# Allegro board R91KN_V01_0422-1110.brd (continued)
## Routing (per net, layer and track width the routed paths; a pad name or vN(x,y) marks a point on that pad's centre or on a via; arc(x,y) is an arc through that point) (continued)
VDDC_LGATE: length 8.5
  TOP w0.8: R622.2 57.77,98.79 57.77,103.8 57.02,104.55 57.02,104.55 56.79,104.78 Q603.4
VDDC_LGATE_CTR: length 3.4
  TOP w0.8: U601.4 61.02,100.26 R615.1 61.01,98.6 R622.1
VDDC_PHASE: length 37.4
  TOP w0.503: 45.61,97.79 L601.1 ; L601.1 45.09,96.36 ; L601.1 45.61,94.93 ; L601.1 48.47,94.93 ; L601.1 47.04,98.31 ; L601.1 48.99,96.36 ; L601.1 47.04,94.4 ; L601.1 48.47,97.79
  TOP w0.8: v2(65.04,107.3) C605.2 65.04,105.76 U601.8
  BOTTOM w1: v2(65.04,107.3) 63.74,106 60.15,106 58.25,107.9 v2(48.55,107.9)
VDDC_SV: length 3.6
  TOP w0.1: R600.2 71.55,98.61 C613.1 70.36,99.8 R611.2
VDDC_UGATE: length 1.7
  TOP w0.8: Q601.4 46.44,104.94 R621.2
VDDC_UGATE_CTR: length 21.8
  TOP w0.8: U601.2 60.17,102.97 59.31,103.84 59.31,104.8 58.22,105.89 58.22,107.8 56.72,109.3 46.79,109.3 45.46,107.97 R621.1
VDDC_VCC: length 4.4
  TOP w0.8: C603.1 64.75,98.27 R607.2 66.73,100.26 U601.5
+DPAB_18: length 19.7
  TOP w0.2: U1.AG8 81.29,65.34 v1(81.29,65.3) 81.37,65.38 81.9,65.38 82.16,65.12 82.16,64.74 81.75,64.33 U1.AG10
  TOP w0.3: 82.28,62.6 v1(82.28,62.6) ; 82.28,62.6 82.26,62.59 82.26,62.45 82.47,62.25 82.47,62.2 82.55,62.11 U1.AF13 ; 82.28,62.6 82.26,62.62 82.26,62.91 U1.AF11 ; U1.AE11 83.35,63.16 83.04,62.86 v1(83.04,62.6) 83.04,62.52 83.35,62.22 U1.AE13
  BOTTOM w0.4: C2511.2 80.66,64.72 81.1,65.16 81.15,65.16 v1(81.29,65.3) 81.48,65.3 82.25,64.53 82.25,63.9 C2513.2 82.27,63.8 82.27,62.67 82.31,62.63 ; 82.31,62.63 82.35,62.59 83.03,62.59 v1(83.04,62.6) ; 82.31,62.63 82.28,62.6 v1(82.28,62.6)
  BOTTOM w0.5: C2511.2 80.56,64.74 C2510.2 79.01,65.31 78.51,65.31 78.5,65.31 78.02,65.31 v4(77.89,65.44) 76.77,65.44 C2512.1 76.54,65.5 74.7,65.5 C2509.1 73.42,64.22 C2514.2 73.42,63.32 B2503.2
+DPAB_VDD10: length 9.7
  TOP w0.3: U1.AF6 U1.AF7 82.55,66.55 v1(82.9,66.2) 82.9,66.15 U1.AF8 82.55,65.74 82.41,65.6 82.41,65.36 82.5,65.27 82.5,65.05 U1.AF9
  BOTTOM w0.4: v1(82.9,66.2) 82.64,66.46 C2517.2
  BOTTOM w0.5: 77.87,66.8 77.9,66.83 78.3,66.83 78.31,66.83 78.8,66.83 78.81,66.83 v4(79.44,66.83) 80.42,66.83 80.48,66.88 C2516.2 80.68,66.8 81.65,66.8 81.99,66.46 C2517.2 ; 77.87,66.8 B2505.2 ; 77.87,66.8 C2515.1
+DPC_18: length 6.9
  TOP w0.2: 87.76,67.01 86.89,67.01 v1(86.56,66.67) 86.51,66.67 86.16,67.03 85.32,67.03 U1.AC6
  TOP w0.25: 87.76,67.01 U1.W6
  TOP w0.3: U1.AC6 U1.AC5
  BOTTOM w0.4: v1(86.56,66.67) 86.56,67.19 B800.2 86.42,67.66 C800.2
+DPC_VDD10: length 8.6
  TOP w0.25: B801.2 C801.2 88.05,72.99 88.05,72.35 87.05,71.35 87.05,70 86.95,69.9 86.95,68.45 86.7,68.2 U1.AA5 U1.AA6
+DPEF_18: length 13.9
  TOP w0.3: U1.AG15 82.35,60.2 v3(82.36,60.2) 82.55,60.01 U1.AF16 81.95,59.6 U1.AG16 81.73,59.4 v3(81.33,58.99) 81.35,58.99 U1.AG17 U1.AG18 U1.AG19
  BOTTOM w0.5: C1504.2 82.23,59.42 82.23,60.07 v3(82.36,60.2) ; B1500.2 75.72,58.7 v4(75.83,58.81) 77,58.81 C1500.1 78.19,58.83 C1501.2 78.36,58.71 79.06,58.71 C1502.2 80.18,58.86 C1503.1 80.74,58.29 C1505.2 81.5,58.81 81.33,58.98 v3(81.33,58.99)
+DPEF_VDD10: length 8.5
  TOP w0.4: v1(82.31,55.34) 82.55,55.11 U1.AF22 82.35,54.6 U1.AG22 U1.AG21 U1.AG20
  BOTTOM w0.4: v1(82.31,55.34) 82.73,54.93 C1508.2
  BOTTOM w0.5: B1502.2 78.45,55.88 79.4,55.88 C1506.1 79.53,55.76 80.55,55.76 C1507.2 81.89,55.77 v1(82.31,55.34)
+DPLL_PVDD: length 11.8
  TOP w0.3: v1(82.68,61.4) 82.68,61.36 82.53,61.2 82.53,60.83 U1.AF14
  BOTTOM w0.3: v1(82.68,61.4) 82.64,61.44 82.07,61.44 81.8,61.71 81.8,61.72 81.58,61.93 81.02,61.93 C59.1
  BOTTOM w0.4: C59.1 C64.1 78.73,62.48 C63.1
  BOTTOM w0.5: B7.2 74.18,62.6 74.18,63.08 74.66,63.56 74.66,63.64 ; C88.1 74.66,63.64 ; 74.66,63.64 74.84,63.64 75.77,62.71 77.82,62.71 C63.1
+DPLL_VDDC: length 18.6
  TOP w0.3: v1(83.55,60.24) 84.1,60.8 U1.AD14
  L3_INNER w0.2: v5(71.86,61.29) 71.87,61.3 74.85,61.3 75.85,60.3 78.85,60.3 79.15,60 81.72,60 82.15,59.56 82.43,59.56 82.86,60 83.31,60 v1(83.55,60.24)
  BOTTOM w0.3: C67.1 82.99,59.7 83.47,60.17 83.47,60.17 v1(83.55,60.24)
  BOTTOM w0.5: v5(71.86,61.29) 71.78,61.37 71.73,61.41 71.73,61.92 C66.1 71.23,62.42 C68.1 70.24,62.59 69.06,62.59 B8.2
+MPV18: length 17.2
  TOP w0.3: U1.L8 94.35,65.86 93.78,66.44 93.78,66.46 93.77,66.46 93.77,66.45 93.76,66.45 93.76,66.46 v1(93.72,66.46)
  BOTTOM w0.4: B12.2 94.02,77.28 C78.1 C77.1 90.83,74.22 91.72,73.33 91.72,70.92 92.83,69.8 C79.1 92.83,66.62 C80.1 93.06,66.46 93.72,66.46 v1(93.72,66.46)
+MVDD: length 290.4
  TOP w0.097: U202.R1 v1(139.56,48.02)
  TOP w0.2: 132.56,78.17 132.49,78.1 v1(131.91,78.1) ; v3(134.77,74.44) 134.75,74.42 134.75,74.2 134.33,73.78 133.83,73.78 133.44,74.17 133.37,74.17 ; v1(139.54,38.24) 139.44,38.24 139.26,38.41 U202.C1 ; 132.56,39.22 132.06,39.22 132.04,39.23 131.13,39.23 130.68,38.78 v1(130.32,38.78)
  TOP w0.3: v1(131.97,70.14) 132.01,70.17 132.56,70.17 ; C122.1 127.04,48.32 v3(127.44,47.91) 127.96,47.4 R203.1 ; 130.3,78.85 C383.1 MC383.1 ; 130.3,78.85 130.32,78.85 v1(130.78,79.3) ; 130.3,78.85 v1(130.72,78.44) ; C125.1 124.07,63.85 v1(123.56,63.34) ; C328.2 121.81,73 v1(122.36,72.45) ; C355.1 139.54,59.16 v1(139.41,59.03) 139.39,59.01 C126.1 ; U1.K23 95.75,53.4 ; U1.K23 95.6,54.05 95.9,54.05 U1.J23 ; U1.K23 95.35,53.78 94.89,53.33 v1(94.88,53.33) 95.2,53 U1.K24 95.75,53.4 ; 95.75,53.4 U1.J24 96.21,53 v1(96.61,53.4) 96.62,53.4 96.62,53.41 96.23,53.8 U1.J23 ; 95.75,53.4 U1.J23 ; v1(97.41,59.05) 97.41,59.17 96.97,59.6 U1.H16 ; 138.16,39.22 138.18,39.22 v1(138.57,39.6) ; v1(117.89,81.44) 117.53,81.08 C351.2 ; v1(144.25,68.3) 143.85,67.9 R205.1 ; U401.E9 139.87,76.58 v1(139.97,76.67) ; C312.2 129.87,40.1 v1(130.14,40.38) 130.3,40.22 130.61,40.22 130.81,40.02 132.56,40.02 ; U401.R9 v1(139.56,68.58) ; v1(142.96,39.46) 142.96,39.49 142.46,39.99 C338.2 ; v1(133.76,43.62) 133.37,44.01 133.37,44.02 ; v3(142.87,54.16) 142.85,54.18 C377.1 ; C344.2 129.97,41.1 130.15,41.27 v1(130.16,41.27) 130.86,41.27 v1(130.87,41.27) ; v1(96.6,61.35) 96.6,61.35 96.95,61.7 U1.H13 ; v1(133.78,77.78) 133.37,77.38 133.37,77.38 ; C373.1 138.77,86.1 v3(139.11,85.75) ; v1(125.36,27.33) 125.81,27.77 C142.1 ; C356.1 136.82,58.75 137.21,58.36 v1(137.59,58.36) ; 133.37,78.97 133.35,78.97 v1(132.96,79.38) 132.56,79.77 132.56,79.78 ; v1(138.57,80.61) 138.57,80.49 138.22,80.14 138.22,79.83 U401.A8 v1(137.76,79.38) ; 132.56,75.78 131.36,75.78 131.12,76.01 131.06,76.01 v1(130.76,76.3) ; v1(123.98,47.62) 123.81,47.45 123.44,47.45 C330.2 ; U1.L22 94.53,54.6 94.03,55.09 v1(94.03,55.1) 94.05,55.1 U1.L21 94.03,56.12 94.03,56.09 94.05,56.09 ; v1(133.76,72.96) 133.75,72.96 133.66,72.87 133.65,72.87 133.53,72.75 133.53,72.75 133.37,72.58 ; 133.37,36.81 v1(133.76,37.22) ; MC365.1 142.74,64.1 v3(142.14,63.49) ; 132.56,46.41 132.53,46.45 131.99,46.45 v1(131.98,46.47) ; v1(131.68,42.47) 132.51,42.47 132.56,42.41 ; C372.1 v1(142.05,75.8) ; 132.56,68.58 131.95,68.58 v1(131.91,68.53) ; C358.1 122.51,65.53 v1(122.3,65.31) ; C326.2 v3(129.85,76.8) ; 137.37,74.97 137.31,74.97 v1(136.94,75.34) ; U202.K2 137.78,43.62 v1(137.76,43.62) ; v1(98.05,44.79) 98.49,44.35 C334.2 ; v1(137.76,42.81) 137.76,42.74 138.09,42.41 U202.H2 ; 132.56,48.02 131.96,48.02 v1(131.91,48.06) ; C309.2 142.46,41.19 142.95,40.7 v1(142.95,40.6) ; 134.16,41.62 134.37,41.62 v1(134.66,41.31) ; U1.K9 95.39,65 v1(95.75,64.64) 96.11,65 U1.J9 ; C305.2 v1(142.05,77.6) ; U1.H19 96.88,57.2 v3(96.28,56.6) ; U1.K10 95.35,64.12 v1(95.72,63.75) ; v1(139.97,40.62) 139.76,40.81 U202.F1 ; v1(119.87,49.7) 119.83,49.74 C332.2 ; C353.2 118.04,65.29 118,65.33 v3(117.91,65.33) ; U1.L11 94.9,63.75 v1(95.72,63.75) ; v3(126.72,70.25) 126.8,70.17 126.8,70.15 C343.2 ; v1(139.16,36.22) 138.97,36.41 U202.A1 138.79,36.81 138.16,37.44 138.16,37.62 ; v1(131.85,37.99) 132.28,38.41 132.56,38.41 ; v1(94.05,56.09) 94.05,56.09 ; 94.05,56.09 U1.L20 ; v1(139.57,78.47) 139.56,78.47 139.27,78.17 U401.C9 ; v1(95.72,63.75) 96.15,64.17 U1.J10 ; C315.2 118.4,49.76 v1(118.45,49.71) ; v1(130.42,36.26) 129.77,36.26 129.31,36.71 C364.1 129.74,37.14 v3(130.35,37.14) ; U401.K8 138.16,72.58 v1(138.57,72.98) ; C371.1 v1(110.34,62) ; v3(144.33,41.67) 143.87,41.67 R211.1 ; U202.N1 v1(139.6,46.41) ; v1(127.49,68.69) 128.14,68.03 C300.2 ; C307.2 v1(142.46,38.21) ; U401.D9 139.56,77.38 v1(139.76,77.58) ; U401.N9 v1(139.6,70.17) ; v3(139.91,74.1) 139.83,74.17 U401.H9
  TOP w0.4: C363.1 142.09,72.94 v1(141.65,72.5) 142.21,71.94 C301.2 ; U1.L13 94.71,61.56 94.71,62.24 U1.L12 94.55,62.47 v1(94.13,62.88) 94.55,63.3 U1.L11 ; v1(130.32,38.78) 130.32,38.73 130.31,38.73 129.81,38.73 C311.2 ; C310.2 130.12,42.1 v1(130.15,42.12) ; v3(142.15,37.4) 142.98,37.4 C379.1 142.7,36.5 v3(142.15,36.5) ; v3(143.51,59.57) 143.07,59.57 C369.1 143.3,61.16 v3(143.39,61.16) ; R201.1 143.95,48.1 144.31,48.1 144.31,48.13 144.32,48.13 144.32,48.11 v3(144.32,48.11) ; v3(142.5,79.27) 143.38,79.27 C368.1 143.11,78.32 v3(142.65,78.32) ; C354.2 v3(141.56,67.03) ; R213.1 127.82,73.94 v1(127.06,73.94) ; C337.2 v1(141.95,74.9) ; C362.1 v1(141.48,73.94) ; C342.2 v1(142.05,76.7) ; v3(141.75,50.1) 142.49,50.1 C366.1 142.48,49.25 v3(141.75,49.25)
  TOP w0.503: 153.84,68.75 C726.1 ; C726.1 156.09,69.88 ; C726.1 156.09,68.75 ; C726.1 154.97,69.88 ; C726.1 156.09,69.31 ; C726.1 153.84,69.88 ; C726.1 153.84,68.19 ; C726.1 155.53,69.88 ; C729.1 162.21,69.88 ; C729.1 161.08,68.19 ; C729.1 161.08,68.75 ; C729.1 163.33,68.75 ; C729.1 163.33,69.88 ; C729.1 163.33,69.31 ; C729.1 162.77,69.88 ; C729.1 161.08,69.88 ; L701.2 163.23,77.98 ; L701.2 163.75,76.55 ; L701.2 161.8,78.5 ; L701.2 160.37,77.98 ; L701.2 160.37,75.12 ; L701.2 161.8,74.6 ; L701.2 163.23,75.12 ; L701.2 159.85,76.55
  BOTTOM w0.1: 132.56,70.17 132.56,70.17 ; 132.56,46.41 132.56,46.42
  BOTTOM w0.2: v1(133.76,72.96) 133.75,72.96 133.37,72.58 133.37,72.58 ; v1(130.76,76.3) 130.85,76.39 131.39,76.39 131.4,76.38 131.79,76.38 131.8,76.39 132.31,76.39 132.31,76.39 132.44,76.39 132.56,76.51 132.56,76.58 ; v1(136.75,77.12) 136.77,77.12 136.91,76.98 137.53,76.98 137.92,77.38 U402.D2 ; v1(133.76,43.62) 133.76,43.61 133.76,43.05 133.37,42.66 133.37,42.41 ; v1(133.76,39.62) 133.76,39.61 133.37,39.22 ; v1(131.85,37.99) 131.94,37.99 132.37,38.41 132.56,38.41
  BOTTOM w0.25: v1(138.57,72.98) 138.16,72.58 U401.K8 ; U202.K2 138.09,44.02 137.81,43.73 137.81,43.68 v1(137.76,43.62)
  BOTTOM w0.3: C136.1 v1(122.3,65.31) ; v3(143.39,61.16) 143.39,61.1 MC381.1 143.08,59.57 v3(143.51,59.57) ; C137.1 94.32,63.64 C135.1 ; C137.1 94.17,62.88 v1(94.13,62.88) ; C137.1 95.34,63.37 v1(95.72,63.75) ; 132.56,74.17 132.48,74.09 131.64,74.09 131.64,74.1 v1(131.63,74.1) 131.53,74.2 C321.2 ; v1(137.59,58.36) 137.59,58.37 C316.2 ; v1(131.97,70.14) 132.01,70.14 132.04,70.17 132.56,70.17 ; C361.1 107.75,49.5 v1(107.75,49.68) ; U402.F1 139.11,75.78 139.63,76.3 139.63,76.34 v1(139.97,76.67) ; C121.1 99.66,47.13 R293.1 ; U402.A1 138.97,79.92 138.88,80.02 138.88,80.35 138.62,80.61 v1(138.57,80.61) ; v1(107.63,71.86) 107.56,71.86 107.07,71.36 C141.1 ; 132.56,36.81 133.01,36.37 v1(133.03,36.37) ; v1(105.53,49.62) 105.53,49.83 C370.1 ; v1(127.4,67.33) 127.06,66.98 C306.2 ; R293.1 99.96,46.87 100.62,46.87 100.8,46.7 v1(100.8,46.69) 100.81,46.69 101.46,46.03 C335.2 ; R293.1 R291.1 ; v3(136.75,41.3) 137.06,41.62 137.37,41.62 ; v1(133.76,43.62) 133.37,44.01 133.37,44.02 ; v1(131.91,78.1) 132.49,78.1 132.56,78.17 ; C314.2 117.12,75.18 117.18,75.12 117.33,75.12 v1(117.56,74.89) ; U402.B2 v1(137.76,79.38) ; C303.2 101.3,73.23 101.23,73.29 v1(101,73.29) ; v3(135.06,75.47) 134.98,75.39 134.98,75.32 134.63,74.97 U402.G7 ; 132.56,40.81 132.43,40.68 132.02,40.68 131.72,40.38 131.29,40.38 130.87,40.8 v1(130.87,41.27) ; 138.97,39.22 138.97,39.23 138.59,39.6 v1(138.57,39.6) 138.57,39.62 138.96,40.02 U201.E9 ; v1(138.17,57.39) 139.02,56.54 R225.2 ; v1(130.14,40.38) 129.87,40.1 C312.2 ; v1(131.91,68.53) 131.95,68.58 132.56,68.58 ; v1(114.49,46.36) 114.77,46.36 115.06,46.07 C333.2 ; v3(127.25,46.03) 127.25,45.98 127.54,45.68 C336.2 ; U202.N1 v1(139.6,46.41) ; C129.1 115.59,34.69 115.91,35.01 115.91,35.58 v1(115.97,35.63) ; v1(94.03,55.1) 94.1,55.1 C120.1 ; v3(122.57,49.41) 123.16,50.01 C374.1 ; v1(103.03,68.44) 103.02,68.45 103.01,68.45 102.99,68.47 102.29,68.47 C128.1 102.24,68.48 C139.1 ; 132.56,77.38 132.54,77.4 132.23,77.4 132.21,77.38 131.97,77.38 v1(131.91,77.45) ; 142.17,49.68 142.12,49.68 141.75,49.3 v3(141.75,49.25) ; 142.17,49.68 v3(141.75,50.1) ; 142.17,49.68 C131.1 ; C127.1 107.44,46.53 107.39,46.59 107.39,47.24 v1(107.62,47.48) ; v1(94.88,53.33) 95.85,54.3 R302.2 95.94,54.26 96.41,53.78 96.41,53.78 96.61,53.58 v1(96.61,53.4) ; v1(139.41,59.03) 140.09,59.03 R227.2 ; U201.A8 138.16,36.06 v1(138.35,35.88) ; v1(117.89,81.44) 117.81,81.53 117.16,81.53 117.14,81.55 C325.2 ; C385.2 100.2,75.44 99.6,75.44 v3(99.6,75.43) ; v3(142.15,64.44) 142.49,64.1 MC367.1 ; v1(110.06,71.47) 110.03,71.48 109.99,71.48 109.62,71.86 C349.2 ; v1(141.6,46.7) 141.63,46.67 141.63,46.28 142.16,45.75 C357.1 ; 132.56,48.02 131.96,48.02 v1(131.91,48.06) ; v1(97.41,59.05) 97.81,59.45 98.26,59.45 98.37,59.34 98.6,59.11 98.81,58.9 C140.1 ; v3(129.93,73.52) 129.71,73.3 C302.2 ; U401.C9 139.26,78.17 v1(139.57,78.47) ; 133.37,79.78 133.34,79.78 133.15,79.58 133.15,79.56 132.97,79.38 132.96,79.38 v1(132.96,79.38) ; v1(131.98,46.47) 132.02,46.42 132.56,46.42 ; C386.2 129.64,78.19 130.48,78.19 v1(130.72,78.44) ; v1(96.6,61.35) 96.68,61.43 C134.1 ; U401.R9 v1(139.56,68.58) ; C339.2 119.8,49.84 119.87,49.77 v1(119.87,49.7) ; C384.2 101.58,43.39 v3(101.6,43.41) ; U202.C1 139.36,38.41 v1(139.54,38.24) ; U202.R1 v1(139.56,48.02) ; U201.H9 139.83,42.41 139.88,42.46 v1(139.9,42.46) ; R207.1 126.88,70.25 v3(126.72,70.25) ; v1(138.56,73.78) 138.56,73.81 138.19,74.17 U402.H2 ; v1(130.15,42.12) 130.12,42.1 C310.2 ; C308.2 114.44,66.2 v1(114.03,65.79) ; 133.37,37.62 v1(133.76,37.22) ; C341.2 124.9,63.75 125.21,64.07 125.21,64.31 125.23,64.32 v1(125.22,64.32) ; v1(130.16,41.27) 129.99,41.1 C344.2 ; v1(130.32,38.78) 130.32,38.73 130.26,38.68 129.86,38.68 C311.2 ; U401.N9 v1(139.6,70.17)
  BOTTOM w0.4: v1(141.41,69.97) 142.42,69.97 C347.2 ; C320.2 v1(141.66,70.99) ; v1(142.95,40.6) 142.46,41.09 C309.2 ; C375.1 v1(141.6,46.7) ; C338.2 142.46,39.96 v1(142.96,39.46) ; C326.2 v3(129.85,76.8) ; v1(95.75,64.64) 95.83,64.56 C124.1 ; v1(141.51,68.97) 142.42,68.97 C348.2 ; C132.1 105.25,67.16 v3(105.25,66.3) ; v3(142.5,79.27) 143.5,79.27 MC133.1 ; C322.2 v1(141.62,47.6) ; v1(141.45,44.3) 141.75,44 C359.1 ; v3(141.72,42.29) 141.86,42.15 142.41,42.15 C340.2 ; C380.1 127.48,48.81 127.48,48.8 127.48,47.95 v3(127.44,47.91) ; C354.2 v3(141.56,67.03) ; C372.1 v1(142.05,75.8) ; C307.2 v1(142.46,38.21) ; v3(142.15,37.4) 142.98,37.4 C379.1 142.69,36.5 v3(142.15,36.5) ; v1(144.25,72.69) 143.68,72.69 R215.1 ; C342.2 v1(142.05,76.7) ; C123.1 124.12,62.93 123.7,63.34 v1(123.56,63.34) ; C337.2 v1(141.95,74.9) ; v3(141.48,67.97) 142.42,67.97 C350.2 ; R209.1 126.75,44.69 126.75,45.11 126.81,45.16 126.81,45.28 126.82,45.3 v3(126.82,45.35) ; C305.2 v1(142.05,77.6) ; C329.2 v3(141.65,43.1)
  BOTTOM w0.5: v3(140.36,84.28) 139.82,84.82 C304.2 ; C138.1 v3(119.45,87.7) ; v3(115.85,87.4) 115.85,88.44 C382.1 114.98,88.52 v3(114.98,87.47) ; v3(142.72,52.92) 143.35,52.92 MC130.1 143.33,54.16 v3(142.87,54.16)
  BOTTOM w0.503: C726.1 156.09,69.31 ; C726.1 156.09,68.75 ; C726.1 153.84,69.88 ; C726.1 154.97,69.88 ; C726.1 155.53,69.88 ; C726.1 153.84,68.75 ; C726.1 156.09,69.88 ; C726.1 153.84,68.19 ; C729.1 162.77,69.88 ; C729.1 162.21,69.88 ; C729.1 161.08,69.88 ; C729.1 163.33,68.75 ; C729.1 163.33,69.88 ; C729.1 161.08,68.19 ; C729.1 163.33,69.31 ; C729.1 161.08,68.75 ; L701.2 163.23,77.98 ; L701.2 160.37,75.12 ; L701.2 159.85,76.55 ; L701.2 163.23,75.12 ; L701.2 160.37,77.98 ; L701.2 161.8,74.6 ; L701.2 161.8,78.5 ; L701.2 163.75,76.55
  vias: v2(151.26,70.44) v2(151.64,72.72) v2(152.4,76.15) v2(152.4,73.87) v2(152.4,71.58) v2(153.16,77.3) v2(153.16,75.01) v2(153.16,72.72) v2(153.16,70.44) v2(153.92,76.15) v2(153.92,73.87) v2(153.92,71.58) v2(154.69,77.3) v2(154.69,75.01) v2(154.69,72.72) v2(154.69,70.44) v2(155.45,76.15) v2(155.45,73.87) v2(155.45,71.58) v2(156.21,77.3) v2(156.21,75.01) v2(156.21,72.72) v2(156.21,70.44) v2(156.97,76.15) v2(156.97,73.87) v2(156.97,71.58) v2(157.73,77.3) v2(157.73,75.01) v2(157.73,72.72) v2(157.73,70.44) v2(158.5,76.15) v2(158.5,73.87) v2(158.5,71.58) v2(159.26,77.3) v2(159.26,75.01) v2(159.26,72.72) v2(159.26,70.44) v2(160.02,73.87) v2(160.02,71.58) v2(160.78,72.72) v2(160.78,70.44) v2(161.54,73.87) v2(161.54,71.58) v2(162.31,72.72) v2(162.31,70.44) v2(163.07,71.58) v3(68.05,94.3) v3(68.05,92.9) v3(68.55,93.7) v3(68.95,92.9) v3(69.45,94.3) v3(69.45,93.5)
+MVDD_SOURCE: length 9.7
  TOP w0.503: C730.1 142.05,92.47 ; C730.1 141.05,93.47 ; C730.1 142.05,91.47 ; C730.1 142.05,93.47 ; C730.1 140.05,92.47 ; C730.1 140.05,91.47 ; C730.1 140.05,93.47 ; C730.1 141.05,91.47
+PCIE_PVDD: length 13.8
  TOP w0.3: U1.AM30 79.28,49 v3(78.33,48.05)
  BOTTOM w0.5: C89.1 76.95,40.7 v4(76.95,42.2) 76.95,43.2 C73.1 ; B11.2 75.65,44.49 75.99,44.15 76,44.15 C73.1 ; C73.1 77.04,43.64 77.04,44.41 78.25,45.62 78.25,46.3 C75.1 ; v3(78.33,48.05) 77.4,47.12 C74.1
  BOTTOM w0.6: C74.1 C75.1
+SPV10: length 6.4
  TOP w0.3: v1(96.55,66.24) 96.55,66.24 96.55,66.23 96.98,65.8 U1.H8
  BOTTOM w0.3: B9.2 94.45,68.49 C70.1 95.03,68.49 MB9.2 95.48,68.5 95.6,68.5 96.1,68 v4(96.1,67.72) 95.59,67.21 C71.1 95.74,66.89 96.27,66.36 96.42,66.36 v1(96.55,66.24)
+SPV18: length 12.3
  TOP w0.3: v1(97.32,67.02) 97.32,67.02 97,66.69 97,66.65 U1.H7
  BOTTOM w0.4: v1(97.32,67.02) 97.32,67.02 97.66,67.36 C62.1 97,68.84 97,69.04 C61.1
  BOTTOM w0.5: C61.1 96.22,69.82 C58.1 96.22,73.26 96.63,73.66 B5.2
A_B_DAC1: length 71.9
  TOP w0.1: U1.AH24 80.7,52.75 80.35,52.75 80.25,52.65 80.05,52.65 79.97,52.73 79.5,52.73 79.33,52.55 78.89,52.55 78.84,52.6 78.82,52.6 ; 24.85,24.5 24.15,24.5
  TOP w0.155: 24.85,24.5 25.05,24.5 26.05,25.5 26.05,27.6 32.8,34.35 32.84,34.35 33.1,34.61 33.1,34.65 47.25,48.8 73.03,48.8 76.83,52.6 78.82,52.6 ; 24.15,24.5 23.64,23.99 R1001.1 22.49,23.99 MR1017.1
A_B_DAC1_F: length 12.1
  TOP w0.1: J1601.C3 6.82,18.16 9,18.16 9.88,19.02 D1002.1 13.22,19.99 C1006.1 15.74,19.99 L1003.2
A_B_DAC2_F: length 20.8
  TOP w0.1: L2003.2 11.65,72.01 C2006.1 12.12,72.5 11.32,73.3 9.45,73.3 8.25,74.5 8.25,80.1 3.94,84.41 MJ1001.3
A_BB_DAC1: length 70.5
  TOP w0.1: 78.82,52.3 78.84,52.3 78.89,52.35 79.41,52.35 79.58,52.52 79.88,52.52 80.03,52.4 80.3,52.4 80.45,52.55 80.7,52.55 81.18,52.25 81.52,52.25 U1.AG25
  TOP w0.155: R1029.1 24.96,23.99 26.35,25.38 26.35,27.48 32.92,34.05 32.96,34.05 33.4,34.49 33.4,34.53 47.37,48.5 73.15,48.5 76.95,52.3 78.82,52.3
A_G_DAC1: length 72.4
  TOP w0.1: 24.85,21 24.15,21
  TOP w0.155: 24.85,21 27.25,23.4 27.25,26.8 48.05,47.6 73.55,47.6 77.9,51.95 79,51.95 79.08,52.04 79.59,52.04 U1.AL25 ; R1016.1 R1002.1 23.64,20.49 24.15,21
A_G_DAC1_F: length 13.6
  TOP w0.1: 8.11,14.37 6.85,15.62 6.85,16.9 7.75,17.8 10.25,17.8 11.03,17.02 D1001.1 13.24,17.02 13.82,17.59 C1005.1 15.74,17.59 L1002.2
A_G_DAC2_F: length 14.5
  TOP w0.1: MJ1001.2 2.9,81.5 3.05,81.5 7.75,76.8 7.75,74.37 9.62,72.5 C2005.1 9.15,72.01 L2002.2
A_GB_DAC1: length 71.2
  TOP w0.155: R1028.1 24.69,20.7 24.97,20.7 27.55,23.28 27.55,26.68 48.17,47.3 73.67,47.3 78.03,51.66 79.12,51.66 79.21,51.74 79.89,51.74 80.32,52.17 80.39,52.17 80.42,52.2 U1.AJ25
A_HSYNC_DAC1: length 70.7
  TOP w0.1: v3(32.65,22.4) 32.65,26.56 48.66,42.57 72.03,42.57 74.21,44.75 74.78,44.75 76.72,46.68 76.72,47.77 79.04,50.1 79.51,50.1 79.52,50.09 79.98,50.09 80.17,50.28 80.65,50.28 80.85,50.48 80.85,51.02 80.95,51.12 U1.AH26
  BOTTOM w0.1: R52.2 30.5,23.85 30.99,24.34 30.99,25.54 31.75,26.3 U1999.2 ; MR52.2 30.48,23.13 30.73,22.88 32.17,22.88 v3(32.65,22.4)
A_HSYNC_DAC1_B: length 6.7
  BOTTOM w0.1: 26.35,29.81 R1010.1 29.55,29.81 31.1,28.26 U1999.3
A_HSYNC_DAC1_C: length 2.2
  BOTTOM w0.1: R1010.2 C1007.1 R1018.1
A_HSYNC_DAC1_R: length 42.3
  BOTTOM w0.1: R1018.2 24.25,29.5 24.75,29 24.75,28.18 25.03,27.9 26.75,27.9 27.05,27.6 27.05,23.98 28.55,22.48 28.55,17.83 27.02,16.3 21.15,16.3 20.23,15.38 D1005.1 13.53,15.38 11.91,17 11.05,17 10.25,17.8 7.65,17.8 6.75,16.9 6.75,15 6.12,14.37 J1601.C4
A_HSYNC_DAC2: length 13.4
  TOP w0.1: R56.2 67.9,60.89 70.05,60.89 71.4,62.24 v4(74.5,62.24) 74.58,62.16 79.38,62.16 U1.AL13
A_HSYNC_DAC2_R: length 77
  BOTTOM w0.1: MR1018.2 23.1,30.96 22.69,30.96 22.03,30.3 16.95,30.3 16.54,30.71 16.54,50.21 15.15,51.6 15.15,66 13.68,67.47 13.68,84.87 10.65,87.9 7.75,87.9 5.02,85.17 3.8,85.17 MJ1001.13
A_R_DAC1: length 74.1
  TOP w0.1: 24.15,17.5 24.85,17.5
  TOP w0.155: R1015.1 R1003.1 23.99,17.5 24.15,17.5 ; 24.85,17.5 25.1,17.75 25.1,19.47 29.45,23.82 29.45,27.1 48.85,46.5 73.59,46.5 77.4,50.31 77.4,50.31 77.97,50.88 78.44,51.34 79.3,51.34 U1.AM26
A_R_DAC1_F: length 9.8
  TOP w0.1: 8.11,16.91 8.78,17.58 10.19,17.58 11.01,16.76 11.01,16.34 11.83,15.53 D1000.1 12.72,15.53 13.05,15.19 C1004.1 15.74,15.19 L1001.2
A_R_DAC2_F: length 12.5
  TOP w0.1: MJ1001.1 2.91,79.83 7.24,75.51 C2004.1 6.75,72.01 L2001.2
A_RB_DAC1: length 72.9
  TOP w0.155: MR1027.1 24.67,17.2 24.97,17.2 25.4,17.63 25.4,19.35 29.75,23.7 29.75,26.98 48.97,46.2 73.71,46.2 77.52,50.01 77.53,50.01 78.1,50.58 78.56,51.05 79.48,51.05 79.83,51.4 U1.AK26
A_VSYNC_DAC1: length 69.7
  TOP w0.1: v3(31.9,22.4) 31.9,26.09 48.58,42.77 71.95,42.77 74.13,44.95 74.7,44.95 76.52,46.77 76.52,47.84 76.53,47.87 76.53,47.88 78.97,50.31 79.58,50.31 79.61,50.28 79.88,50.28 80.09,50.49 80.44,50.49 U1.AJ27
  BOTTOM w0.1: U1999.5 29.8,26.15 30.48,25.47 R51.2 30.48,24.83 29.97,24.32 29.97,23.08 30.65,22.4 v3(31.9,22.4)
A_VSYNC_DAC1_B: length 5
  BOTTOM w0.1: R1011.1 27.16,29.1 28.95,29.1 29.15,28.9 U1999.6
A_VSYNC_DAC1_C: length 2.6
  BOTTOM w0.1: R1011.2 C1008.1 25.24,27.41 R1019.1
A_VSYNC_DAC1_R: length 32.9
  BOTTOM w0.1: J1601.8 9.71,20.08 12.72,17.07 D1006.1 19.38,17.07 19.95,16.5 26.93,16.5 28.35,17.92 28.35,22.4 24.25,26.5 R1019.2
A_VSYNC_DAC2: length 15
  TOP w0.1: U1.AJ13 80.21,61.8 79.88,61.48 79.62,61.48 79.57,61.52 79.57,61.52 79.26,61.83 76.14,61.83 75.9,61.59 73.44,61.59 v4(73.2,61.37) 72.74,61.37 71.77,60.39 70.24,60.39 69.12,59.27 69.11,59.27 68.68,58.84 68.01,58.84 R43.2
A_VSYNC_DAC2_R: length 80.7
  BOTTOM w0.1: MR1019.2 23.26,29.31 23.75,29.8 23.75,31.2 23.65,31.3 22.75,31.3 21.95,30.5 17.05,30.5 16.88,30.67 16.88,50.27 15.35,51.8 15.35,66.2 13.95,67.6 13.95,84.9 10.75,88.1 7.67,88.1 5.5,85.93 MJ1001.14
AUX1_BYPSS_EN: length 16.3
  TOP w0.1: Q1803.3 v3(30.35,79) ; Q1802.1 24.84,89.21 v3(25.15,88.9) ; Q1801.1 v3(25.35,85.36)
  BOTTOM w0.1: v3(30.35,79) 30.35,79.8 25.35,84.8 v3(25.35,85.36) 25.35,85.6 25.05,85.9 25.05,86.89 R1804.2 25.65,87.9 25.15,88.4 v3(25.15,88.9)
AUX2N: length 63.2
  TOP w0.11: v1(84.53,63.68) 84.53,63.65 84.15,63.27 U1.AD11 ; v1(67.82,76.59) 67.56,76.33 43.82,76.33 34.42,85.72 33.92,85.72 C2541.1
  BOTTOM w0.11: v1(84.53,63.68) 84.53,63.65 84.58,63.7 84.58,65.54 84.53,65.58 84.53,67.11 82.24,69.4 81.6,69.4 79.27,71.73 77.75,71.73 74.14,75.34 70.91,75.34 69.92,76.33 68.08,76.33 v1(67.82,76.59)
AUX2P: length 64
  TOP w0.1: U1.AD13 84.15,62.43 v1(84.35,62.63)
  TOP w0.11: v1(67.82,75.82) 67.56,76.08 43.72,76.08 34.32,85.47 33.92,85.47 C2535.1
  BOTTOM w0.11: v1(67.82,75.82) 68.08,76.08 69.82,76.08 70.81,75.09 74.04,75.09 77.65,71.48 79.17,71.48 81.49,69.15 82.13,69.15 84.28,67 84.28,65.48 84.33,65.43 84.33,64.11 84.12,63.91 84.12,62.85 v1(84.35,62.63)
B_DAC2: length 53.6
  TOP w0.155: v3(13.14,66.75) 12.86,66.47 12.47,66.47 R2001.1 C2003.1 11.65,68.19 L2003.1 ; MR1017.2 v3(23.45,24.99)
  BOTTOM w0.155: v3(23.45,24.99) 23.45,25.3 19.45,29.3 16.43,29.3 14.08,31.65 14.08,62.88 12.22,64.74 12.22,66.14 12.55,66.47 12.86,66.47 v3(13.14,66.75)
BA0: length 113.2
  TOP w0.097: 138.16,45.62 138.11,45.67 137.79,45.67 137.51,45.96 137.27,45.96 137.26,45.95 137.07,45.95 137.06,45.96 136.95,45.96 136.75,46.16 136.5,46.16 136.38,46.28 136.38,50.01 136.5,50.14 136.62,50.14 136.69,50.23 136.91,50.47 136.91,50.8 136.68,51.03 136.04,51.46 135.9,51.53 135.42,51.53 133.87,53.08 132.46,53.08 132.02,53.51 131.55,53.51 v3(131.32,53.74) 130.27,54.79 130.05,54.79 129.84,55 129.84,55.22 129.64,55.42 129.36,56.03 129.22,56.33 129.22,59.74 129.41,59.92 129.41,60.23 129.41,60.24 129.41,60.37 129.53,60.49 129.57,60.49 129.56,60.49 129.56,60.43 129.69,60.3 129.86,60.3 129.99,60.43 129.99,60.74 130.25,61.01 130.25,61.25 130.42,61.42 130.56,61.42 130.68,61.54 130.68,61.87 130.74,61.93 130.89,61.93 131,62.04 131,62.2 130.89,62.3 130.81,62.3 130.68,62.43 130.68,62.67 v1(130.71,62.7) 131.2,63.19 134.53,63.19 135.91,64.56 136.44,64.56 136.73,64.84 137.25,64.84 137.79,65.38 v1(137.79,65.78) ; 133.37,70.97 133.37,71.03 132.99,71.4 132.45,71.4 132.35,71.5 130.96,71.5 130.7,71.24 129.83,71.24 129.11,70.52 129.11,70.31 129.61,69.81 129.61,68.58 v1(129.78,68.42)
  TOP w0.1: 129.57,60.49 v1(129.58,60.49)
  TOP w0.15: 95.75,60.63 95.75,60.97
  TOP w0.17: v1(95.92,61.37) 95.78,61.37 95.68,61.27 95.68,61.03 95.75,60.97 ; U1.J16 95.92,59.6 95.69,59.84 95.69,60.57 95.75,60.63
  BOTTOM w0.097: v3(131.32,53.74) 131.32,53.76 131.13,53.56 131.13,52.34 129.38,50.59 129.38,49.87 129.87,49.38 129.87,48.93 130.08,48.73 130.08,47.61 130.15,47.53 130.15,46.79 130.92,46.02 132.97,46.02 133.37,45.62 ; v1(137.79,65.78) 137.79,66.28 137.58,66.49 136.94,67.12 136.8,67.26 136.63,67.44 136.63,69.69 137.02,70.08 137.02,70.31 137.22,70.52 137.32,70.52 137.32,70.52 138.51,70.52 138.63,70.64 138.63,70.82 138.62,70.83 138.62,71.04 138.51,71.15 138.29,71.15 138.16,71.03 U402.M2 ; v1(129.78,68.42) 129.84,68.42 130.11,68.14 130.11,67.55 129.94,67.38 129.94,66.91 129.66,66.64 129.66,65.69 129.81,65.54 129.81,63.6 130.02,63.39 130.16,63.39 130.28,63.27 130.28,63.18 130.3,63.16 130.3,62.83 130.29,62.82 130.29,62.32 130.47,62.15 130.81,62.15 130.94,62.27 130.94,62.58 130.81,62.7 v1(130.71,62.7)
  BOTTOM w0.1: 100.7,62.15 98.89,62.15 98.82,62.22 97.72,62.22 97.08,61.58 97.08,61.26 96.77,60.95 96.35,60.95 v1(95.92,61.37)
  BOTTOM w0.2: v1(129.58,60.49) 129.56,60.51 129.56,60.57 129.66,60.67 v4(130.96,60.67) 131.61,60.67 131.73,60.54 131.73,60.07 131.61,59.95 129.54,59.95 129.41,59.82 129.41,59.78 129.29,59.66 112.95,59.66 112.83,59.78 112.83,60.15 112.65,60.33 110.43,60.33 110.3,60.2 110.3,59.97 110.29,59.96 110.29,59.78 110.17,59.66 109.49,59.66 107.55,61.59 107.55,61.59 107.52,61.62 103.89,61.62 103.18,62.34 102.34,62.34 102.15,62.15 100.7,62.15
BA1: length 111.2
  TOP w0.097: 133.37,46.41 133.35,46.41 132.97,46.03 131.8,46.03 v1(131.12,46.72) ; U401.N8 138.16,70.5 138.29,70.62 138.41,70.62 138.57,70.46 138.57,70.4 138.62,70.35 138.62,69.86 138.49,69.73 137.24,69.73 136.83,69.32 136.83,67.55 137.14,67.24 137.34,67.24 137.56,67.02 137.56,67.02 137.87,66.71 138.28,66.71 138.86,66.12 139.62,66.12 139.71,66.03 139.71,65.2 139.62,65.11 138.35,65.11 138.15,64.91 137.62,64.91 137.39,64.67 137.39,64.65 137.35,64.61 137.21,64.61 137.2,64.63 136.86,64.63 136.85,64.61 136.84,64.61 136.63,64.4 136.62,64.4 136.54,64.32 136.47,64.32 v1(136.3,64.15) 135.88,64.15 134.66,62.94 131.32,62.94 131.19,62.81 131.19,62.68 131.19,62.68 131.19,62.34 131.19,62.34 131.19,62.33 131.23,62.29 131.23,61.94 131.19,61.91 131.19,61.63 131.13,61.55 130.87,61.29 130.22,60.64 130.22,60.53 130.22,60.53 130.22,60.41 130.22,60.41 130.22,60.23 130.1,60.11 130.06,60.11 130,60.04 130,59.87 130.06,59.8 130.1,59.8 130.22,59.68 130.22,59.53 130.1,59.41 129.91,59.41 v1(129.88,59.43) 129.88,59.54 129.73,59.69 129.53,59.69 129.45,59.61 129.45,58.48 129.59,58.34 129.59,58.25 129.45,58.11 129.45,57.95 129.59,57.81 129.59,57.65 129.45,57.51 129.45,57.35 129.59,57.21 129.59,57.05 129.45,56.91 129.45,56.75 129.59,56.61 129.59,56.37 129.6,56.28 129.6,56.08 129.84,55.55 131.23,54.16 131.5,54.16 131.92,53.75 132.12,53.75 132.38,53.49 v1(132.62,53.49) 132.82,53.28 133.95,53.28 135.5,51.73 135.95,51.73 136.02,51.7 136.15,51.63 136.8,51.19 136.95,51.04 137.13,50.87 137.16,50.34 137.16,50.19 137.19,50.21 137.19,50.2 v1(137.2,50.2)
  TOP w0.2: v1(94.1,59.95) 94.1,59.94 94.55,60.38 U1.L15
  BOTTOM w0.097: 133.37,70.17 133.41,70.22 133.66,70.22 133.78,70.33 133.78,70.49 133.65,70.61 133.18,70.61 132.93,70.36 132.92,70.36 132.92,69.91 133.04,69.78 134.25,69.78 134.66,69.36 134.66,69.24 134.53,69.11 134.53,68.98 134.62,68.89 134.74,68.89 134.96,69.11 135.09,69.11 135.3,68.89 135.3,66.06 135.88,65.47 135.88,65.13 135.88,65.12 135.88,64.79 135.88,64.78 135.88,64.4 136.13,64.15 v1(136.3,64.15) ; v1(131.12,46.72) 131.12,46.92 130.87,47.17 130.87,47.48 130.54,47.8 130.54,48.15 130.78,48.38 130.78,48.7 130.34,49.13 130.34,49.58 130.41,49.65 130.41,50.62 131.91,52.11 131.91,52.59 132.26,52.95 132.26,53.13 v1(132.62,53.49) ; v1(137.2,50.2) 137.11,50.28 136.84,50.28 136.75,50.19 136.75,49.99 136.66,49.9 136.36,49.9 136.28,49.81 136.28,49.69 136.36,49.6 136.66,49.6 136.75,49.51 136.75,49.39 136.66,49.3 136.36,49.3 136.28,49.21 136.28,49.09 136.36,49 136.66,49 136.75,48.91 136.75,47.35 137.24,46.86 137.46,46.86 137.82,46.5 138.08,46.5 U201.N8
  BOTTOM w0.1: v1(94.1,59.95) 94.12,59.98 94.31,59.98 94.32,59.98 94.62,59.98 94.74,60.1 94.74,60.23 94.62,60.36 94.57,60.36 94.45,60.48 94.45,60.62 94.57,60.74 94.77,60.74 94.84,60.82 94.84,61.09 94.74,61.19 94.47,61.19 94.35,61.31 94.35,61.55 94.53,61.72 94.53,61.77 94.65,61.9 95.11,61.9 95.23,61.77 95.23,61.66 95.37,61.52 95.37,60.91 95.47,60.81 95.69,60.81 95.75,60.75 96.85,60.75 97.28,61.18 97.28,61.5 97.8,62.02 98.61,62.02 98.81,61.81
  BOTTOM w0.2: 98.81,61.81 102.29,61.81 102.48,62.01 102.98,62.01 103.33,61.66 103.33,61.39 103.43,61.29 107.37,61.29 107.4,61.26 107.41,61.26 109.35,59.32 110.53,59.32 110.62,59.41 110.62,59.82 110.64,59.84 110.64,59.87 110.77,59.99 111.09,59.99 111.21,59.87 111.21,59.45 111.34,59.32 111.69,59.32 111.81,59.45 v4(111.81,59.62) 111.81,59.8 111.94,59.93 112.33,59.93 112.45,59.8 112.45,59.45 112.58,59.32 129.8,59.32 129.88,59.41 v1(129.88,59.43)
BA2: length 112.3
  TOP w0.097: 137.37,45.62 137.37,45.56 137.24,45.44 137.13,45.44 136.92,45.64 136.92,45.71 136.67,45.96 136.3,45.96 136.18,46.09 136.18,49.94 135.98,50.13 135.98,50.34 136.11,50.47 136.11,50.83 135.88,51.06 135.54,51.06 135.54,51.06 135.31,51.06 135.12,51.25 135.12,51.25 133.86,52.5 133.86,52.52 133.71,52.68 133.23,52.68 133.23,52.68 131.98,52.68 131.98,52.69 130.73,52.69 130.66,52.76 v3(130.66,53.2) 130.6,53.15 130.26,53.15 130.11,53.29 128.76,56.22 128.75,56.25 128.75,59.39 v1(128.34,60.49) 128.71,60.49 128.95,60.73 128.95,60.75 129.13,60.94 129.13,62.23 v1(129.9,62.99) 129.89,62.99 129.89,63.22 130.33,63.66 134.32,63.66 134.33,63.66 134.34,63.66 134.54,63.88 134.54,63.88 136.02,65.36 136.89,65.36 v1(137.01,65.48) ; v1(129.65,67.72) 130.18,68.25 130.18,68.59 129.9,68.88 129.9,69.39 130.22,69.71 130.22,69.83 129.83,70.22 129.83,70.34 129.92,70.43 130.04,70.43 130.43,70.04 130.55,70.04 130.64,70.13 130.64,70.25 130.25,70.64 130.25,70.77 130.34,70.85 130.46,70.85 130.85,70.47 130.93,70.47 131.06,70.59 131.06,71.2 131.12,71.27 131.3,71.27 131.43,71.14 131.43,70.76 131.55,70.63 133.82,70.63 U401.M3
  TOP w0.17: v1(97.35,62.72) 97.55,62.72 97.75,62.92 U1.G11
  BOTTOM w0.097: 137.37,70.97 137.37,71.14 137.27,71.23 137.14,71.23 137.13,71.24 137.09,71.24 136.98,71.14 136.98,70.89 136.9,70.81 136.79,70.81 136.71,70.89 136.71,71.17 136.64,71.24 136.46,71.24 136.39,71.17 136.39,70.7 136.51,70.58 136.65,70.58 136.77,70.45 136.77,70.25 136.65,70.12 136.5,70.12 136.43,70.05 136.43,67.35 136.67,67.12 136.72,67.06 136.86,66.92 136.86,66.92 137.15,66.64 137.15,66.64 137.38,66.41 137.38,65.85 v1(137.01,65.48) ; v1(129.65,67.72) 129.63,67.71 129.63,67.28 129.43,67.07 129.43,65.59 129.57,65.45 129.57,63.32 129.89,63.01 129.89,62.99 v1(129.9,62.99) ; v3(130.66,53.2) 130.58,53.2 130.58,52.12 129.15,50.69 129.15,50.69 129.15,49.78 129.64,49.29 129.64,48.84 129.84,48.63 129.84,46.77 131.44,45.16 133.53,45.16 133.98,45.62 134.16,45.62
  BOTTOM w0.2: v1(128.34,60.49) 128.33,60.49 128.19,60.35 126.07,60.35 125.76,60.66 125.15,60.66 125.15,60.66 124.59,60.66 124.59,60.66 122.93,60.66 122.93,60.66 120.97,60.66 120.96,60.66 113.64,60.66 113.27,61.03 113.27,61.11 113.15,61.23 112.91,61.23 112.9,61.23 112.44,61.23 112.31,61.36 112.31,61.87 112.19,61.99 111.56,61.99 111.44,61.87 111.44,61.39 111.31,61.27 111.31,61.15 111.19,61.02 110.92,61.02 110.8,61.15 110.8,62.36 110.92,62.48 111.18,62.48 111.28,62.59 111.28,62.92 111.18,63.02 109.98,63.02 109.86,62.9 109.86,61.81 109.73,61.69 109.28,61.69 109.16,61.81 109.16,62.84 108.96,63.03 108.56,63.03 108.36,62.84 108.36,62.45 108.23,62.32 107.68,62.32 107.56,62.45 107.56,62.91 107.44,63.03 106.88,63.03 106.76,62.91 106.76,62.45 106.63,62.32 106.08,62.32 105.96,62.45 v4(105.96,62.63) 105.96,62.94 105.86,63.03 105.25,63.03 105.16,62.94 105.16,62.38 105.03,62.26 104.48,62.26 104.36,62.38 104.36,62.84 104.16,63.03 102.22,63.03 101.87,63.39 100.17,63.39 100.01,63.23 99.01,63.23 98.51,62.72 v1(97.35,62.72)
BB_DAC2: length 50
  TOP w0.155: v3(23.85,25.7) 23.85,25.61 MR1029.2 ; v3(13.14,65.89) 12.86,66.17 12.42,66.17 R2029.1
  BOTTOM w0.155: v3(23.85,25.7) 23.47,25.7 19.57,29.6 16.55,29.6 14.38,31.77 14.38,63.01 12.52,64.87 12.52,66.02 12.67,66.17 12.86,66.17 v3(13.14,65.89)
CASA#0: length 67.3
  TOP w0.097: 137.37,44.02 137.37,43.8 137.36,43.79 137.36,43.66 137.24,43.55 136.97,43.55 136.84,43.67 136.84,43.92 136.32,44.45 135.82,44.45 135.7,44.58 135.7,44.63 135.72,44.65 135.72,44.67 135.57,44.81 135.57,49.5 135.58,49.5 135.58,49.66 134.79,50.45 134.79,50.45 133.48,51.75 129.13,51.75 126.92,53.96 126.92,54.98 126.41,55.48 125.95,55.48 125.85,55.58 125.85,55.72 125.97,55.85 126.54,55.85 126.62,55.93 126.62,56.05 126.54,56.13 125.91,56.13 125.81,56.23 125.81,56.36 125.91,56.46 126.45,56.46 126.54,56.55 126.54,56.67 126.45,56.76 125.89,56.76 125.81,56.84 125.81,57.22 125.94,57.34 126.05,57.34 126.16,57.23 126.57,57.23 126.67,57.13 126.67,56.99 126.7,56.96 126.7,56.88 126.82,56.76 127.52,56.76 127.93,57.16 127.93,57.76 128.03,57.86 128.18,57.86 128.28,57.76 128.28,56.55 128.16,56.43 126.95,56.43 126.86,56.34 126.86,56.21 126.95,56.13 128.16,56.13 128.28,56 128.28,55.86 128.18,55.76 127.38,55.76 v5(127.2,55.58)
  TOP w0.1: U1.G19 98.3,57.2 98.45,57.35 v1(98.94,57.35) ; v1(135.78,44.65) 135.72,44.65
  BOTTOM w0.097: U201.K3 134.32,44.17 134.32,44.49 134.51,44.67 134.51,44.78 134.77,44.94 134.82,44.94 135.56,44.94 135.68,44.81 135.68,44.65 v1(135.78,44.65)
  BOTTOM w0.1: v5(127.2,55.58) 127.11,55.58 126.94,55.75 106.42,55.75 105.25,56.92 104.96,56.92 104.96,56.91 101.26,56.91 101.16,57.02 101.16,57.12 100.75,57.53 100.08,57.53 100.06,57.55 99.03,57.55 98.94,57.46 v1(98.94,57.35)
CASA#1: length 64.2
  TOP w0.097: v3(128.47,65.79) 133.73,65.79 133.76,65.81 133.76,65.81 134.56,66.61 134.56,66.83 135.11,67.37 135.11,70.34 135.51,70.75 135.51,71.11 135.28,71.34 135.12,71.34 134.81,71.66 134.77,71.66 134.65,71.78 134.65,72.24 134.63,72.25 134.63,72.31 134.57,72.38 134.47,72.38 134.41,72.31 134.41,72.24 134.28,72.12 134.02,72.12 133.99,72.08 133.81,72.08 133.74,72.02 133.61,72.02 133.52,72.11 133.52,72.24 133.71,72.43 133.71,72.49 133.77,72.56 133.93,72.56 134.03,72.66 134.08,72.66 U401.K3 ; v1(126.67,62.15) 126.62,62.1 126.62,61.4 126.65,61.38 126.65,58.84 126.62,58.81 126.62,58.64 126.33,58.34 v1(126.33,57.62)
  TOP w0.1: v1(97.97,60.27) 97.75,60.04 U1.G16 ; 134.82,71.64 v3(134.82,71.66)
  BOTTOM w0.097: 137.37,72.58 136.59,72.39 135.66,72.11 v3(134.82,71.66)
  BOTTOM w0.1: v1(97.97,60.27) 98.24,60 99.58,60 99.59,59.99 99.59,59.99 99.64,59.99 100.6,59.02 102.17,59.02 102.62,58.57 105.94,58.57 106.61,57.9 126.06,57.9 126.32,57.62 v1(126.33,57.62) ; v1(126.67,62.15) 126.67,61.74 126.54,61.62 126.48,61.62 126.43,61.67 126.25,61.85 126.1,61.85 125.97,61.99 125.97,62.36 126.07,62.47 126.26,62.47 126.4,62.6 126.4,62.84 126.57,63.02 126.57,63.23 126.5,63.29 126.39,63.29 126.27,63.41 126.27,63.55 126.4,63.67 126.47,63.67 126.54,63.75 126.54,63.86 126.47,63.93 126.31,63.93 126.27,63.97 126.27,64.11 126.51,64.35 126.51,64.44 126.56,64.49 126.72,64.49 127.12,64.09 127.24,64.09 127.33,64.18 127.33,64.3 126.68,64.96 126.68,65.08 126.76,65.17 126.89,65.17 127.54,64.51 127.66,64.51 127.75,64.6 127.75,64.73 127.53,64.95 127.53,65.07 127.62,65.16 127.75,65.16 127.97,64.94 128.14,64.94 128.25,65.05 128.25,65.24 128.13,65.37 128.1,65.37 127.97,65.49 127.97,65.56 128.26,65.84 128.41,65.84 v3(128.47,65.79)
CEC1: length 2.8
  TOP w0.1: MJ2501.13 12.56,56.91 TP1700.1
CEDAR_NC: length 5.8
  TOP w0.3: U1.AA12 86.74,62.4 86.29,61.95 v1(86.22,61.95)
  TOP w0.4: U1.U11 89.5,63.4 89.45,63.45 88.99,63.45 88.94,63.4 U1.V11 88.54,63.61 87.96,63.61 U1.Y11 87.65,63.5 86.85,63.5 U1.AA11 86.7,63.35 86.7,62.67 86.75,62.62 U1.AA12
  BOTTOM w0.4: R72.1 85.73,61.47 v1(86.22,61.95)
CKEA0: length 83.5
  TOP w0.097: v3(134.75,58.02) 135.44,57.34 135.44,57.02 136.22,56.23 v3(136.22,56.02)
  TOP w0.1: v3(131.19,44.14) 131.31,44.02 132.56,44.02
  TOP w0.2: v1(95.75,55.55) 95.35,55.95 U1.K20
  BOTTOM w0.097: U201.K9 139.08,43.9 139.85,43.9 141.18,45.23 v4(141.18,45.53) 141.18,47.9 141.2,47.92 141.2,52.3 142.39,53.49 142.39,54.57 140.94,56.02 v3(136.22,56.02) 135.6,56.02 135.38,56 134.51,55.81 133,54.38 132.96,54.36 132.26,54.16 131.5,54.16 131.5,54.16 131.14,54.16 131.14,54.16 131.01,54.16 130.93,54.08 130.85,54.02 130.09,53.25 130.07,53.25 129.74,52.92 129.71,52.72 129.71,52.41 128.68,50.9 128.68,48.74 128.85,48.46 128.87,48.43 129.24,47.83 129.3,47.63 129.32,47.31 129.32,46.56 131.19,44.69 v3(131.19,44.14)
  BOTTOM w0.1: v3(134.75,58.02) 134.42,58.02 132.94,56.53 131.07,56.53 130.66,56.12 129.9,56.12 128.42,54.65 126.8,54.65 126.46,54.99 126.27,54.99 126.07,54.97 125.84,54.87 125.6,54.64 125.26,54.64 125,54.91 124.92,54.91 124.91,54.92 124.69,54.92 105.3,54.92 104.07,56.15 102.51,56.15 102.19,55.83 102.19,55.82 101.85,55.48 98.87,55.48 98.47,55.6 98.12,55.79 97.47,55.94 96.14,55.94 v1(95.75,55.55)
CKEA1: length 74.7
  TOP w0.097: U401.K9 138.97,72.58 139.09,72.7 139.66,72.7 139.79,72.58 139.79,72.33 139.66,72.2 137.83,72.2 137.83,72.2 137.41,72.2 137.4,72.2 136.79,72.2 136.67,72.08 136.67,70.05 136.22,69.61 136.22,66.72 v1(135.98,66.48) 135.98,66.33 134.06,64.41 130.09,64.41 128.87,63.19 128.24,63.19 128.05,62.99 128.05,61.68 127.93,61.56 127.5,61.56 127.24,61.3 127.24,60.31 127.38,60.18 127.61,60.18 127.7,60.09 127.7,59.96 127.61,59.88 127.3,59.88 127.24,59.82 127.24,59.64 127.3,59.58 128.15,59.58 128.2,59.52 128.23,59.44 128.23,59.36 128.15,59.28 127.34,59.28 127.25,59.19 127.25,59.06 127.34,58.98 128.2,58.98 128.28,58.89 128.28,58.76 128.2,58.68 127.32,58.68 127.23,58.59 127.23,58.47 127.32,58.39 128.22,58.39 128.28,58.33 128.28,58.18 128.22,58.12 127.19,58.12 127.07,57.99 127.07,57.81 127.19,57.69 v1(127.53,57.69)
  TOP w0.1: U1.J17 96.15,58.5 v1(96.71,59.05)
  BOTTOM w0.097: 132.56,72.58 132.65,72.58 132.79,72.42 132.84,72.42 133.12,72.14 133.44,72.14 133.47,72.12 133.5,72.12 133.82,71.8 133.82,70.83 134.02,70.63 134.57,70.63 134.86,70.34 135.36,70.34 135.51,70.5 135.68,70.5 135.77,70.4 135.77,66.98 135.98,66.77 v1(135.98,66.48)
  BOTTOM w0.1: v1(96.71,59.05) 97.44,59.79 99.56,59.79 100.52,58.82 102.09,58.82 102.57,58.34 105.84,58.34 106.52,57.66 125.72,57.66 126.16,57.23 126.5,57.23 126.73,57.45 126.73,57.47 127.11,57.85 127.34,57.85 127.51,57.67 127.51,57.69 v1(127.53,57.69)
CLK_27M: length 3.2
  BOTTOM w0.1: NR75.1 66.32,70.17 TR75.1 MR75.1 66.41,69.09 U12.9
CLK_100M: length 3.3
  BOTTOM w0.1: U12.5 70.84,67.59 R75.1 72.55,68.38 R74.1 73.44,68.38 R73.1
CLKA0: length 66.5
  TOP w0.12: 134.16,43.22 134.28,43.22 134.4,43.09 134.47,43.09 134.79,42.77 136.2,42.77 v3(136.43,42.99) 136.43,43.73 136.12,44.03 135.36,44.03 135.09,44.3 135.09,49.46 133.45,51.1 128.06,51.1 R221.1 127.07,50.98 125.17,50.98 125.16,50.99 125.04,50.99 124.8,51.23 124.8,51.24 124.52,51.52 124.52,55.59 125.04,56.12 125.04,57.48 124.76,57.77 121.43,57.77 121.14,57.48 121.14,56.52 122,55.66 122,51.63 122.38,51.24 v1(122.38,51.1) ; U1.H26 v1(97.38,50.98)
  BOTTOM w0.12: v1(122.38,51.1) 122.25,51.23 114.01,51.23 114,51.23 113.84,51.23 113.83,51.23 103.43,51.23 102.91,50.7 99.17,50.7 98.41,51.47 97.87,51.47 v1(97.38,50.98)
  BOTTOM w0.13: 137.37,43.22 v3(136.43,42.99)
CLKA1: length 66.7
  TOP w0.12: v3(121.65,62.65) 121.68,62.65 122.13,63.09 122.58,63.09 122.84,62.84 122.84,60.23 122.56,59.96 121.05,59.96 120.92,59.84 120.92,59.19 121.14,58.98 125.26,58.98 125.56,59.27 125.56,60.99 125.26,61.3 124.66,61.3 124.37,61.59 124.37,63.43 124.83,63.9 127.06,63.9 R223.1 128.04,63.88 128.58,63.88 129.8,65.11 133.97,65.11 135.18,66.31 135.18,66.75 135.67,67.24 135.67,70.06 136.1,70.5 136.1,71.38 135.47,72.01 135.46,72.01 135.04,72.42 135.04,72.98 135.06,73 v3(135.06,73.02) 135.06,73.17 135.16,73.27 135.51,73.27 135.54,73.3 137.29,73.3 137.37,73.36 137.37,73.38 ; v1(98.16,65.44) 98.04,65.44 97.75,65.15 U1.G9
  BOTTOM w0.12: v3(121.65,62.65) 121.68,62.68 121.68,63.03 121.38,63.33 114.24,63.33 112.55,65.02 104.68,65.02 103.36,66.34 99.04,66.34 98.15,65.73 v1(98.16,65.44)
  BOTTOM w0.13: v3(135.06,73.02) 134.47,73.02 134.16,73.32 U402.J7
CLKA#0: length 67.1
  TOP w0.12: U202.K7 134.16,43.8 134.18,43.79 134.18,43.72 134.34,43.55 134.52,43.37 134.59,43.37 134.9,43.06 135.87,43.06 136.09,43.27 136.09,43.42 135.98,43.52 v3(135.98,43.52) 135.75,43.76 135.24,43.76 134.81,44.19 134.81,49.34 133.33,50.82 128.17,50.82 127.65,50.3 R222.2 127.18,50.7 125.05,50.7 125.04,50.72 124.92,50.72 124.52,51.12 124.52,51.12 124.24,51.4 124.24,55.71 124.76,56.23 124.76,57.36 124.64,57.48 121.54,57.48 121.42,57.36 121.42,56.64 122.28,55.78 122.28,51.68 122.44,51.51 122.96,51.51 123.08,51.38 v1(123.08,51.33) ; v1(97.35,51.75) 96.81,51.75 96.7,51.85 96.7,52.1 96.81,52.2 U1.H25
  BOTTOM w0.12: v1(123.08,51.33) 122.89,51.52 113.89,51.52 113.88,51.51 113.72,51.51 113.72,51.51 103.32,51.51 102.8,50.98 99.29,50.98 98.52,51.75 v1(97.35,51.75)
  BOTTOM w0.13: v3(135.98,43.52) 137.37,44.02
CLKA#1: length 67.3
  TOP w0.12: 137.37,72.58 137.39,72.58 137.49,72.67 137.49,72.92 137.39,73.02 135.66,73.02 135.56,72.92 v3(135.56,72.53) 135.56,72.29 136.38,71.46 136.38,70.38 135.95,69.94 135.95,67.12 135.46,66.63 135.46,66.2 134.08,64.83 129.92,64.83 128.69,63.6 128.43,63.6 128.43,63.6 128.07,63.6 R224.2 127.38,63.08 126.84,63.62 124.94,63.62 124.65,63.31 124.65,61.71 124.78,61.58 125.38,61.58 125.84,61.11 125.84,59.16 125.38,58.7 121.01,58.7 120.99,58.71 120.99,58.73 120.64,59.08 120.64,59.95 120.93,60.24 122.44,60.24 122.56,60.35 122.56,62.49 122.5,62.55 122.5,62.55 v3(122.4,62.66) ; U1.H9 v1(97.39,65.39)
  BOTTOM w0.12: v3(122.4,62.66) 122.4,62.69 121.47,63.61 114.36,63.61 112.67,65.3 104.8,65.3 103.47,66.62 98.95,66.62 97.99,65.96 97.95,65.96 97.65,65.66 97.65,65.65 v1(97.39,65.39)
  BOTTOM w0.13: U402.K7 134.2,72.54 135.53,72.54 135.54,72.53 v3(135.56,72.53)
CLKTESTA: length 8.9
  TOP w0.1: v1(95.73,65.42) 95.73,65.42 95.73,65.42 U1.K8
  BOTTOM w0.1: v1(95.73,65.42) 95.37,65.78 95.37,66.3 95.11,66.55 94.3,66.55 93.3,67.56 93.3,71.34 C94.1
CLKTESTB: length 6.7
  TOP w0.1: U1.L7 94.72,66.97 v1(94.9,66.97)
  BOTTOM w0.1: C95.1 93.52,71.98 93.52,67.75 94.3,66.97 v1(94.9,66.97)
CSA#0_0: length 68
  TOP w0.097: v1(127.73,54.21) 127.65,54.21 127.52,54.34 127.52,54.62 127.65,54.74 128.13,54.74 128.22,54.84 128.22,54.98 128.13,55.08 127.87,55.08 127.76,55.19 127.76,55.34 127.87,55.45 128.41,55.45 128.53,55.33 128.53,54.8 128.66,54.67 128.9,54.67 129.01,54.56 129.03,54.52 129.03,54.39 128.86,54.22 128.74,54.22 128.48,54.47 128.36,54.47 128.26,54.38 128.26,54.25 128.52,53.99 128.52,53.88 128.44,53.8 128.31,53.8 128.24,53.86 128.13,53.86 128.01,53.74 128.01,53.65 128.1,53.56 128.1,53.46 128,53.36 128,53.24 128.09,53.15 128.21,53.15 129.08,54.01 129.2,54.01 129.29,53.93 129.29,53.8 128.42,52.93 128.42,52.81 128.51,52.72 128.63,52.72 129.37,53.45 129.49,53.45 129.55,53.4 129.58,53.33 129.58,53.24 129.2,52.87 129.2,52.83 129.41,52.62 129.41,52.6 129.45,52.57 129.63,52.57 129.98,52.22 133.58,52.22 134.95,50.85 134.96,50.85 135.19,50.62 135.19,50.62 135.31,50.5 135.98,49.83 135.98,45.67 136.1,45.55 136.5,45.55 136.51,45.56 136.66,45.56 136.84,45.38 136.84,45.31 136.97,45.19 137.3,45.19 137.38,45.27 137.51,45.27 137.54,45.3 137.67,45.44 137.85,45.44 137.98,45.3 137.98,45.12 137.9,45.04 137.9,45.04 137.77,44.91 137.77,44.74 137.54,44.51 137.54,44.33 137.68,44.19 137.86,44.19 138.02,44.36 138.27,44.36 138.41,44.49 138.41,44.69 138.28,44.81 U202.L2
  TOP w0.1: U1.H22 96.95,54.25 96.9,54.2 96.65,54.2 96.57,54.12 96.43,54.12 96.32,54.23 96.32,54.37 96.55,54.6 96.55,54.99 97.01,55.45 97.25,55.45 v1(97.26,55.44) ; v3(136.5,45.53) 136.5,45.55
  BOTTOM w0.097: 133.37,44.81 133.68,44.81 134.02,45.16 134.22,45.16 134.69,45.62 136.26,45.62 136.35,45.53 v3(136.5,45.53)
  BOTTOM w0.1: v1(97.26,55.44) 97.7,55 98.98,55 101.95,55 102.69,55.74 103.85,55.74 105.14,54.45 124.59,54.45 124.68,54.36 124.87,54.17 125.06,54.17 125.06,54.17 126.44,54.17 126.48,54.21 v1(127.73,54.21)
CSA#1_0: length 82.4
  TOP w0.097: v1(128.82,67.73) 128.83,67.73 128.83,67.76 128.8,67.76 128.8,67.8 128.82,67.83 128.82,67.89 128.95,68.02 129.13,68.02 129.38,68.26 129.38,68.97 129.05,69.3 v4(129.05,69.48) 128.88,69.66 128.88,70.62 129.47,71.22 129.47,71.34 129.26,71.55 129.26,71.68 129.35,71.77 129.48,71.77 129.69,71.56 130.43,71.56 130.61,71.73 132,71.73 132.13,71.86 132.13,72.11 132.25,72.24 132.42,72.24 132.42,72.23 132.71,72.23 132.71,72.24 133.19,72.24 133.32,72.11 133.32,72.03 133.37,71.98 133.37,71.78 ; v1(128.72,62.53) 128.84,62.53 129.03,62.72 129.06,62.72 130.27,63.92 134.26,63.92 135.89,65.56 136.52,65.56 136.98,66.02 v1(136.98,66.24)
  TOP w0.1: U1.G13 98.23,62 98.36,62.12 98.36,62.34 98.23,62.47 98.23,63.18 98.13,63.28 98.13,63.86 v1(98.15,63.86)
  BOTTOM w0.097: v1(128.72,62.53) 128.91,62.53 129.03,62.65 129.03,64.81 129.1,64.89 129.1,65.24 128.93,65.42 128.93,66.69 128.92,66.69 128.92,66.95 128.79,67.08 128.56,67.08 128.14,67.49 127.8,67.49 127.8,67.49 127.57,67.73 127.48,67.73 127.35,67.85 127.35,68.14 127.48,68.26 127.68,68.26 127.94,68 128.72,68 128.82,67.9 v1(128.82,67.73) ; v1(136.98,66.24) 136.98,66.34 136.17,67.16 136.17,71.23 136.38,71.44 137.22,71.44 137.41,71.42 137.52,71.46 137.59,71.51 U402.L2
  BOTTOM w0.1: v1(98.15,63.86) 98.14,63.86 98.48,64.2 99.25,64.2 100.01,64.96 101.34,64.96 101.36,64.97 101.94,64.97 101.95,64.96 102.47,64.96 102.49,64.94 102.53,64.94 102.67,64.8 102.81,64.8 102.89,64.89 103.06,64.89 103.18,64.77 103.18,64.77 103.18,64.69 103,64.52 103,64.46 103.47,63.99 112.2,63.99 113.77,62.42 119.5,62.42 119.5,62.42 119.79,62.42 120.59,61.62 126.15,61.62 126.26,61.51 126.41,61.35 126.81,61.35 127.01,61.56 129.19,61.56 129.31,61.68 129.31,61.91 129.19,62.03 128.43,62.03 128.3,62.16 128.3,62.77 128.18,62.9 127.25,62.9 127.13,63.02 127.13,63.49 127.23,63.59 127.36,63.59 127.46,63.49 127.46,63.31 127.58,63.18 128.31,63.18 128.41,63.28 128.41,63.42 128.31,63.52 127.82,63.52 127.69,63.65 127.69,63.72 127.78,63.82 128.14,63.82 128.21,63.88 128.21,64.26 128.52,64.58 128.6,64.58 128.72,64.45 128.72,62.54 v1(128.72,62.53)
CTF2_GAT: length 6.6
  TOP w0.1: R4405.1 R4407.2 100.6,104.56 Q4400.1
CTF2_TRIP: length 14.4
  TOP w0.1: R4402.1 R4404.2 99.59,108.95 94.49,108.95 R4403.1 94.45,106.89 C4400.1 96.03,105.21 Q4401.1
CTF2_VCNTL: length 23.7
  TOP w0.1: R4406.1 91.27,99.67 102.46,99.67 103.27,100.48 103.27,104.62 Q4400.3 101.1,106.35 99.66,107.79 R4404.1
CTF_BYPASS: length 128.8
  TOP w0.1: v3(90.63,99.22) 90.2,98.79 R4058.2 88.88,98.79 88.81,98.86 R4408.2 89.05,100.21 R4406.2 ; R4057.2 144.54,26.6 v3(143.85,26.6) ; R4062.2 R4052.2 107.35,97.32 108.15,98.12 v3(108.15,98.8)
  BOTTOM w0.1: v3(143.85,26.6) 144.61,26.6 146.05,28.04 146.05,82.29 129.54,98.8 v3(108.15,98.8) 101.99,98.8 100.83,99.95 91.36,99.95 v3(90.63,99.22)
CTF_FB_CNTL: length 13.7
  TOP w0.1: v3(107.82,94.64) 107.06,93.88 106.2,93.88 104.97,95.11 R4046.1 ; Q4007.1 v3(114.32,95.76)
  BOTTOM w0.1: v3(107.82,94.64) 108.94,95.76 v3(114.32,95.76)
CTF_GATED2: length 55.5
  TOP w0.1: R4044.2 R4040.2 115.37,100.75 Q4007.3 114.72,100.1 111.65,100.1 111.12,100.63 Q4006.3 110.69,97.14 v3(110.92,96.9) ; R4065.2 72.67,89.99 72.67,91.64 v3(73.61,92.58)
  BOTTOM w0.1: v3(110.92,96.9) 102.18,96.9 99.82,94.54 75.57,94.54 v3(73.61,92.58)
CTF_SET2: length 13.1
  TOP w0.1: R4043.1 113.46,105.9 Q4014.2 Q4008.1 114.51,104.06 115.55,105.1 116.85,105.1 117.92,104.03 C4014.2 C4013.2
CTF_SET3: length 17.6
  TOP w0.1: R4044.1 119.31,100 v3(119.86,100) ; Q4009.1 v3(105.17,100.25)
  BOTTOM w0.1: v3(119.86,100) 111.15,100 110.9,100.25 v3(105.17,100.25)
CTF_TRIP: length 17.6
  TOP w0.1: R4039.1 R4038.2 100.25,91.31 100.76,91.82 100.76,92.96 101.75,93.95 105.56,93.95 106.03,93.48 108.46,93.48 110.29,95.3 110.29,97.05 109.75,97.59 Q4006.1
CTF_VCNTL: length 11.1
  TOP w0.1: R4052.1 106.4,96.56 C4015.1 ; Q4009.3 C4015.1 ; C4015.1 R4046.2 104.81,96.56 R4047.1 R4060.1 102.04,95.57 101.77,95.3 R4045.2
CUR_VDDCT_ADJ_0: length 10.4
  TOP w0.1: U4050.8 64.67,91.44 65.03,91.8 66.62,91.8 66.95,92.13 66.95,94.2 68.05,95.3 69.65,95.3 70.35,96 R4078.1
DACT_A0: length 3.9
  TOP w0.1: R4077.1 65.48,92.04 63.96,92.04 63.74,91.81 63.74,91.23 63.94,91.04 U4050.9
DACT_A1: length 4.5
  TOP w0.1: U4050.11 64.37,90.25 63.88,90.25 63.3,90.83 63.3,91.94 63.92,92.56 MR4076.2 R4076.1
DACT_CLK: length 1.7
  TOP w0.1: R4071.2 68.6,89.44 U4050.2
DACT_DATA: length 1.6
  TOP w0.1: U4050.1 68.92,89.04 R4070.2
DACT_FS0: length 1.8
  TOP w0.1: U4050.7 67.81,91.44 68.38,92 R4073.1
DACT_FS1: length 1.6
  TOP w0.1: R4072.1 68.21,90.9 68.07,91.04 U4050.6
DDC1CLK: length 87.1
  TOP w0.099: U1.AE6 83.35,67.58 83.48,67.71 83.69,67.71 83.92,67.94 83.92,68.4 83.84,68.48 83.84,68.78 83.9,68.83 83.9,69.24 83.84,69.29 83.84,69.62 84.02,69.8 84.02,71.93 83.52,72.44 83.52,72.47 83.5,72.49
  TOP w0.11: R2009.1 16.92,90.22 17.58,90.22 R2008.2 18.53,90.22 19.69,90.22 21.51,92.05 24.69,92.05 28.27,88.47 35.51,88.47 44.15,79.83 62.53,79.83 66.72,84.02 70.11,84.02 72.29,81.84 72.29,79.45 75.01,76.73 79.26,76.73 83.5,72.49
DDC1DATA: length 86.3
  TOP w0.099: U1.AE5 83.35,68.06 83.5,67.91 83.61,67.91 83.72,68.02 83.72,68.32 83.64,68.4 83.64,68.86 83.7,68.92 83.7,69.15 83.64,69.21 83.64,69.7 83.82,69.89 83.82,71.85 83.38,72.3 83.34,72.3 83.33,72.31
  TOP w0.11: 83.33,72.31 79.16,76.48 74.9,76.48 72.04,79.35 72.04,81.74 70,83.77 66.83,83.77 62.64,79.58 44.04,79.58 35.41,88.22 28.17,88.22 24.59,91.8 21.62,91.8 19.79,89.97 18.53,89.97 R2005.2 17.58,89.97 16.92,89.97 R2006.1
